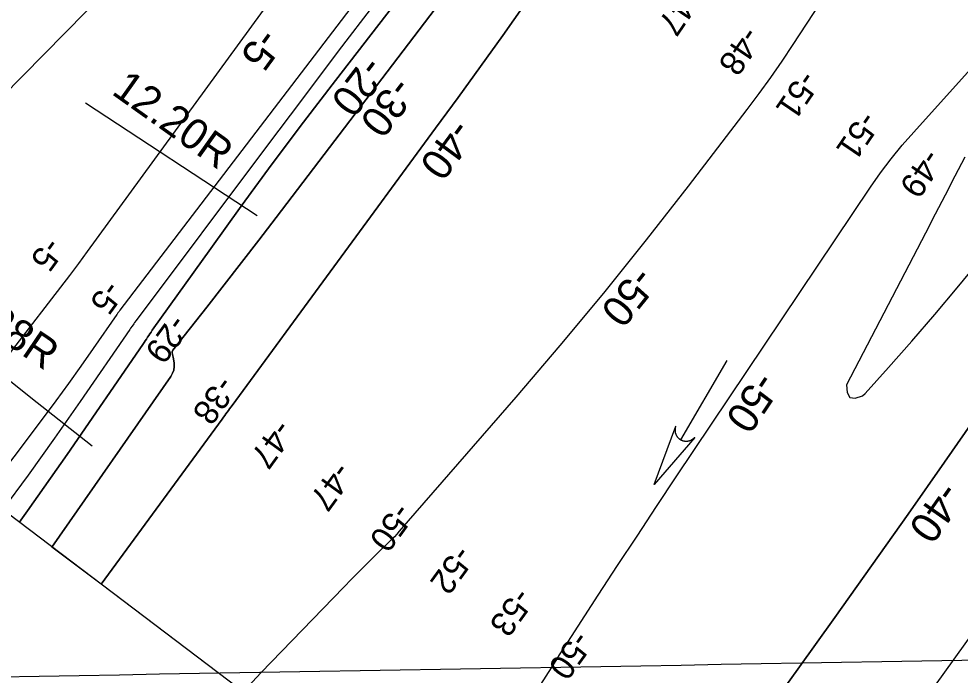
# Model space of a CAD drawing. Extents: x 3905714 to 3926767, y 183354 to 205755.
# Drawn here: x 3912230 to 3913514, y 187283 to 188179 of the extents above; entities that cross this region are included whole.
import ezdxf

# ---------------------------------------------------------------- set-up
doc = ezdxf.new("R2010")
doc.units = 0
for name, color, linetype in [('V-GRID-FRAM', 7, 'Continuous'), ('V-GRID-MAJR', 7, 'Continuous'), ('V-LEVE-TOET', 7, 'Continuous'), ('V-RIVR-RANG', 7, 'Continuous'), ('V-STRM-FLOW', 7, 'Continuous'), ('V-STRM-FMON', 7, 'Continuous'), ('V-TOPO-DPTH', 7, 'Continuous'), ('V-TOPO-MAJR', 7, 'Continuous'), ('V-TOPO-MAJR-IDEN', 7, 'Continuous'), ('V-TOPO-MINR', 7, 'Continuous'), ('V-TOPO-MINR-IDEN', 7, 'Continuous')]:
    doc.layers.add(name, color=color, linetype=linetype)

msp = doc.modelspace()

# ---------------------------------------------------------------- linework, layer by layer
at = {"layer": 'V-GRID-FRAM'}
msp.add_lwpolyline([(3924287.8, 196971.1), (3915521.4, 185005.6), (3909313.3, 189695.8), (3918205.9, 201877.9), (3924287.8, 196971.1)], dxfattribs=at)
at = {"layer": 'V-GRID-MAJR'}
msp.add_spline([(3911382.6, 187267), (3914884.1, 187327.4), (3918088.4, 187383)], degree=3, dxfattribs=at)
at = {"layer": 'V-LEVE-TOET'}
msp.add_line((3912321.3, 188063.8), (3912555.1, 187910.1), dxfattribs=at)
msp.add_lwpolyline([(3912099.4, 187779.9), (3912246.6, 187662.2), (3912330.1, 187596)], dxfattribs=at)
at = {"layer": 'V-STRM-FLOW'}
msp.add_line((3913195.9, 187712.5), (3913132.6, 187604.5), dxfattribs=at)
msp.add_lwpolyline([(3913151.9, 187607.7), (3913096.8, 187543.4), (3913126, 187622.9), (3913125.5, 187621.4), (3913125.3, 187620), (3913125.2, 187619.4), (3913125.1, 187618.9), (3913125.1, 187618.3), (3913125.1, 187617.6), (3913125.1, 187617.1), (3913125.1, 187616.4), (3913125.2, 187615.6), (3913125.3, 187615.2), (3913125.4, 187614.6), (3913125.5, 187613.9), (3913125.7, 187613.4), (3913125.9, 187612.8), (3913126, 187612.4), (3913126.2, 187612), (3913126.4, 187611.5), (3913126.6, 187611), (3913126.8, 187610.6), (3913127, 187610.2), (3913127.3, 187609.7), (3913127.7, 187609.2), (3913127.9, 187608.8), (3913128.2, 187608.4), (3913128.5, 187608), (3913128.8, 187607.7), (3913129, 187607.4), (3913129.4, 187607.1), (3913129.7, 187606.7), (3913130.1, 187606.4), (3913130.5, 187606), (3913130.8, 187605.7), (3913131.2, 187605.4), (3913131.6, 187605.2), (3913132.1, 187604.9), (3913132.6, 187604.5), (3913132.8, 187604.4), (3913133.1, 187604.3), (3913133.4, 187604.1), (3913133.7, 187603.9), (3913134, 187603.8), (3913134.3, 187603.7), (3913134.7, 187603.5), (3913135, 187603.4), (3913135.3, 187603.3), (3913135.7, 187603.1), (3913136, 187603.1), (3913136.6, 187602.9), (3913136.9, 187602.8), (3913137.2, 187602.8), (3913137.6, 187602.7), (3913137.9, 187602.6), (3913138.3, 187602.6), (3913138.8, 187602.5), (3913139.2, 187602.5), (3913139.5, 187602.4), (3913139.8, 187602.4), (3913140.2, 187602.4), (3913140.5, 187602.4), (3913140.9, 187602.4), (3913141.3, 187602.5), (3913141.7, 187602.5), (3913142.2, 187602.5), (3913142.6, 187602.6), (3913143, 187602.7), (3913143.4, 187602.7), (3913143.7, 187602.8), (3913144.1, 187602.9), (3913144.6, 187603), (3913144.6, 187603), (3913144.9, 187603.1), (3913145.1, 187603.2), (3913145.4, 187603.3), (3913145.8, 187603.5), (3913146.2, 187603.6), (3913146.4, 187603.7), (3913146.8, 187603.9), (3913147.1, 187604), (3913147.4, 187604.2), (3913147.7, 187604.3), (3913148.1, 187604.6), (3913148.4, 187604.7), (3913148.5, 187604.8), (3913148.7, 187604.9), (3913148.9, 187605.1), (3913149.2, 187605.3), (3913149.5, 187605.5), (3913149.7, 187605.7), (3913150, 187605.9), (3913150.3, 187606.1), (3913150.5, 187606.3), (3913150.8, 187606.6), (3913151.1, 187606.9), (3913151.3, 187607.1), (3913151.5, 187607.3), (3913151.7, 187607.5), (3913151.8, 187607.6)], close=True, dxfattribs=at)
at = {"layer": 'V-TOPO-DPTH'}
for p, q in [((3912342.5, 187407.2), (3912275.5, 187457.9)), ((3913012.1, 186901.3), (3912342.5, 187407.2))]:
    msp.add_line(p, q, dxfattribs=at)
for points in [[(3912230.8, 187491.6), (3912242.1, 187507.5), (3912296, 187584.5), (3912399.5, 187734.5), (3912401.1, 187736.9), (3912402.7, 187739.3), (3912404.3, 187741.7), (3912405.9, 187744.1), (3912407.4, 187746.6), (3912409, 187749), (3912410.7, 187751.3), (3912412.3, 187753.7), (3912491.9, 187865.2), (3912533.6, 187923), (3912575.9, 187980.6), (3912618.7, 188037.6), (3912662, 188094.3), (3912876.5, 188372)], [(3912876.5, 188372), (3912662, 188094.3), (3912618.7, 188037.6), (3912575.9, 187980.6), (3912533.6, 187923), (3912491.9, 187865.2), (3912412.3, 187753.7), (3912410.7, 187751.3), (3912409, 187749), (3912407.4, 187746.6), (3912405.9, 187744.1), (3912404.3, 187741.7), (3912402.7, 187739.3), (3912401.1, 187736.9), (3912399.5, 187734.5), (3912296, 187584.5), (3912242.1, 187507.5), (3912230.8, 187491.6)], [(3912275.5, 187457.9), (3912437.7, 187690.6), (3912440, 187695), (3912441.6, 187699.5), (3912442.1, 187704.3), (3912441.9, 187709.3), (3912440.7, 187716.9), (3912439.9, 187720.8), (3912439.4, 187723.3), (3912439.5, 187724.4), (3912440.5, 187726.6), (3912486.5, 187785.3), (3912510.3, 187815.7), (3912534, 187846.2), (3912557.5, 187876.8), (3912581, 187907.5), (3912905.6, 188333.9)], [(3912275.5, 187457.9), (3912437.7, 187690.6), (3912440, 187695), (3912441.6, 187699.5), (3912442.1, 187704.3), (3912441.9, 187709.3), (3912440.7, 187716.9), (3912439.9, 187720.8), (3912439.4, 187723.3), (3912439.5, 187724.4), (3912440.5, 187726.6), (3912486.5, 187785.3), (3912510.3, 187815.7), (3912534, 187846.2), (3912557.5, 187876.8), (3912581, 187907.5), (3912905.6, 188333.9)], [(3912720, 188242.3), (3912368, 187781), (3912366.9, 187779.5), (3912365.4, 187777.3), (3912364.3, 187775.9), (3912363.8, 187775.1), (3912331.7, 187728.7), (3912315, 187704.8), (3912298.1, 187681.1), (3912280.9, 187657.5), (3912263.5, 187634.2), (3912183.1, 187527.7)], [(3912920.1, 188198.6), (3912890.1, 188156), (3912859.9, 188113.6), (3912829.4, 188071.4), (3912798.7, 188029.3), (3912521.1, 187651.1), (3912519.4, 187648.8), (3912517.7, 187646.5), (3912516.1, 187644.2), (3912514.4, 187641.9), (3912512.7, 187639.6), (3912511, 187637.3), (3912509.3, 187635), (3912507.6, 187632.7), (3912342.5, 187407.2)], [(3912342.5, 187407.2), (3912507.6, 187632.7), (3912509.3, 187635), (3912511, 187637.3), (3912512.7, 187639.6), (3912514.4, 187641.9), (3912516.1, 187644.2), (3912517.7, 187646.5), (3912519.4, 187648.8), (3912521.1, 187651.1), (3912798.7, 188029.3), (3912829.4, 188071.4), (3912859.9, 188113.6), (3912890.1, 188156), (3912920.1, 188198.6)], [(3913637.6, 187782), (3913492.7, 187573.9), (3913443, 187503), (3913393.2, 187432.3), (3913343, 187361.8), (3913292.6, 187291.4), (3913215.3, 187184.1)], [(3913637.6, 187782), (3913492.7, 187573.9), (3913443, 187503), (3913393.2, 187432.3), (3913343, 187361.8), (3913292.6, 187291.4), (3913215.3, 187184.1)], [(3913340.1, 187074.7), (3913673.5, 187539)], [(3913340.1, 187074.7), (3913673.5, 187539)]]:
    msp.add_lwpolyline(points, dxfattribs=at)
at = {"layer": 'V-TOPO-MAJR'}
for points in [[(3913922.1, 189057), (3913485.5, 188448), (3913285.8, 188143.3), (3913270.7, 188120.8), (3913255.3, 188098.5), (3913239.3, 188076.5), (3913223.1, 188054.8), (3913143, 187950.3), (3913085.8, 187877), (3913027.7, 187804.5), (3912968.2, 187733), (3912907.9, 187662.3), (3912749, 187479.5), (3912745.7, 187475.8), (3912742.4, 187472.2), (3912738.9, 187468.6), (3912735.5, 187465.2), (3912719.1, 187449.3), (3912707.5, 187437.9), (3912696, 187426.4), (3912684.5, 187414.8), (3912673.1, 187403.1), (3912560.9, 187286.9), (3912536.4, 187260.7)], [(3912937.9, 187264.3), (3912960.6, 187299.8), (3912964.2, 187305.4), (3912967.8, 187311), (3912971.4, 187316.5), (3912975, 187322.1), (3913020.4, 187392.2), (3913046.7, 187432.7), (3913073.3, 187473.1), (3913100, 187513.4), (3913126.8, 187553.7), (3913391.8, 187948.8), (3913405.5, 187968.4), (3913419.8, 187987.5), (3913434.9, 188006), (3913450.6, 188024.1), (3913527.9, 188109.8)], [(3913520.4, 187990), (3913506.9, 187964.1), (3913493.4, 187938.1), (3913479.9, 187912.2), (3913466.5, 187886.2), (3913359.1, 187679.4), (3913359.8, 187668.9), (3913363.3, 187662.2), (3913370.7, 187661.3), (3913380.9, 187664.1), (3913384.2, 187667.6), (3913416.3, 187703.1), (3913448, 187738.8), (3913479.2, 187775.1), (3913509.9, 187811.8), (3913548.5, 187858.5)]]:
    msp.add_lwpolyline(points, dxfattribs=at)
at = {"layer": 'V-TOPO-MINR'}
for points in [[(3912092.7, 187955.9), (3912664.7, 188537.1)], [(3912876.5, 188372), (3912662, 188094.3), (3912618.7, 188037.6), (3912575.9, 187980.6), (3912533.6, 187923), (3912491.9, 187865.2), (3912412.3, 187753.7), (3912410.7, 187751.3), (3912409, 187749), (3912407.4, 187746.6), (3912405.9, 187744.1), (3912404.3, 187741.7), (3912402.7, 187739.3), (3912401.1, 187736.9), (3912399.5, 187734.5), (3912296, 187584.5), (3912242.1, 187507.5), (3912230.8, 187491.6)], [(3912905.6, 188333.9), (3912581, 187907.5), (3912557.5, 187876.8), (3912534, 187846.2), (3912510.3, 187815.7), (3912486.5, 187785.3), (3912440.5, 187726.6), (3912439.5, 187724.4), (3912439.4, 187723.3), (3912439.9, 187720.8), (3912440.7, 187716.9), (3912441.9, 187709.3), (3912442.1, 187704.3), (3912441.6, 187699.5), (3912440, 187695), (3912437.7, 187690.6), (3912275.5, 187457.9)], [(3912619.7, 188268), (3912323.5, 187861.2), (3912311.5, 187844.9), (3912299.3, 187828.6), (3912287.1, 187812.5), (3912274.8, 187796.4), (3912204.5, 187705.5)], [(3912720, 188242.3), (3912368, 187781), (3912366.9, 187779.5), (3912365.4, 187777.3), (3912364.3, 187775.9), (3912363.8, 187775.1), (3912331.7, 187728.7), (3912315, 187704.8), (3912298.1, 187681.1), (3912280.9, 187657.5), (3912263.5, 187634.2), (3912183.1, 187527.7)], [(3912715.1, 188199), (3912665.9, 188134.3), (3912616.9, 188069.4), (3912568, 188004.4), (3912390.3, 187767.2), (3912388.1, 187764.2), (3912387, 187762.6), (3912384.9, 187759.5), (3912382.7, 187756.4), (3912381.7, 187754.8), (3912314, 187656.7), (3912278.7, 187606.4), (3912243, 187556.3), (3912208.1, 187508.8)], [(3912920.1, 188198.6), (3912890.1, 188156), (3912859.9, 188113.6), (3912829.4, 188071.4), (3912798.7, 188029.3), (3912521.1, 187651.1), (3912519.4, 187648.8), (3912517.7, 187646.5), (3912516.1, 187644.2), (3912514.4, 187641.9), (3912512.7, 187639.6), (3912511, 187637.3), (3912509.3, 187635), (3912507.6, 187632.7), (3912342.5, 187407.2)], [(3913215.3, 187184.1), (3913292.6, 187291.4), (3913343, 187361.8), (3913393.2, 187432.3), (3913443, 187503), (3913492.7, 187573.9), (3913637.6, 187782)], [(3913340.1, 187074.7), (3913673.5, 187539)]]:
    msp.add_lwpolyline(points, dxfattribs=at)

# ---------------------------------------------------------------- texts
at = {"layer": 'V-RIVR-RANG'}
for s, rotation, p in [('-47', 235.8032, (3913136, 188224.8)), ('-48', 235.8032, (3913219.3, 188170.3)), ('-51', 235.8032, (3913297.5, 188110.2)), ('-51', 235.8032, (3913379.9, 188054.7)), ('-49', 235.8032, (3913466.3, 188003.5)), ('-5', 233.8683, (3912268.2, 187882.7)), ('-5', 233.8683, (3912349.2, 187824)), ('-29', 233.8683, (3912439, 187777.4)), ('-38', 234.006, (3912503.5, 187693.8)), ('-47', 234.006, (3912581.9, 187633.9)), ('-47', 234.006, (3912662.7, 187576.2)), ('-50', 234.006, (3912744.8, 187520.5)), ('-52', 234.006, (3912827.5, 187462.5)), ('-53', 234.006, (3912908.7, 187404.8)), ('-50', 234.006, (3912988.9, 187346))]:
    msp.add_text(s, height=33.5, rotation=rotation, dxfattribs=at).set_placement(p)
at = {"layer": 'V-STRM-FMON'}
for s, rotation, p in [('12.20R', 324.5702, (3912355.3, 188076.8)), ('12.28R', 325.8638, (3912116.2, 187799.9))]:
    msp.add_text(s, height=42, rotation=rotation, dxfattribs=at).set_placement(p)
at = {"layer": 'V-TOPO-MAJR-IDEN'}
for rotation, p in [(231.3089, (3913072, 187843.2)), (236.1539, (3913237.2, 187699.6))]:
    msp.add_text('-50', height=41.5, rotation=rotation, dxfattribs=at).set_placement(p)
at = {"layer": 'V-TOPO-MINR-IDEN'}
for s, rotation, p in [('-5', 233.9357, (3912560, 188168.4)), ('-20', 232.316, (3912703, 188130.4)), ('-30', 232.7197, (3912742.2, 188102.2)), ('-40', 233.7198, (3912822.6, 188044.3)), ('-40', 235.0061, (3913488.1, 187549.3))]:
    msp.add_text(s, height=41.5, rotation=rotation, dxfattribs=at).set_placement(p)

doc.saveas('drawing.dxf')
